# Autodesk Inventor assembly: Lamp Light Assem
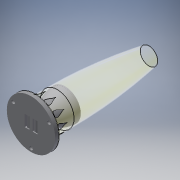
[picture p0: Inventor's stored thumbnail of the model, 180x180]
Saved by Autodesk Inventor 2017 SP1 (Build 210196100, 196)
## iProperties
Created: 2016-12
Part Number: Lamp Light Assem
Document SubType Name: Assembly
Designer: HP_ELITE
Author: HP_ELITE
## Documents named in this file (7)
- C:\Users\HP_ELITE\Google Drive\Projects\Art\Lamp\oiu voroni- TV\Lamp Light Assem.iam
- C:\Users\HP_ELITE\Google Drive\Projects\Art\Lamp\oiu voroni- TV\MR16.ipt
- C:\Users\HP_ELITE\Google Drive\Projects\Art\Lamp\oiu voroni- TV\Bulb Holder Test.ipt
- C:\Users\HP_ELITE\Google Drive\Projects\Art\Lamp\oiu voroni- TV\scaled fixed no supp.ipt
- C:\Users\HP_ELITE\Google Drive\Projects\Art\Lamp\oiu voroni- TV\Defuser.ipt
- C:\Users\HP_ELITE\Google Drive\Projects\Art\Lamp\oiu voroni- TV\Base Plate.ipt
- C:\Users\HP_ELITE\Google Drive\Projects\Art\Lamp\oiu voroni- TV\STL Cut.ipt
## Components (6 placed, 6 different names)
1. MR16:1 — Rigid:1, Mate:2
2. Bulb Holder Test:1 — Rigid:1, Mate:5
3. scaled fixed no supp:1 — Flush:2, Mate:1
4. Defuser:1 — Mate:3, Flush:3, Flush:4, Flush:6, Flush:7
5. Base Plate:1 — Flush:4, Mate:4, Flush:5, Mate:5, Flush:6, Flush:8, Mate:6
6. STL Cut:1 — Flush:7, Flush:8, Mate:6
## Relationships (14: Flush 7, Mate 6, WeldJoint 1)
- Flush:2: scaled fixed no supp:1
- Mate:1: scaled fixed no supp:1
- Rigid:1 [WeldJoint]: MR16:1 ↔ Bulb Holder Test:1
- Mate:2: MR16:1
- Mate:3: Defuser:1
- Flush:3: Defuser:1
- Flush:4: Defuser:1 ↔ Base Plate:1
- Mate:4: Base Plate:1
- Flush:5: Base Plate:1
- Mate:5: Bulb Holder Test:1 ↔ Base Plate:1
- Flush:6: Defuser:1 ↔ Base Plate:1
- Flush:7: Defuser:1 ↔ STL Cut:1
- Flush:8: Base Plate:1 ↔ STL Cut:1
- Mate:6: Base Plate:1 ↔ STL Cut:1
